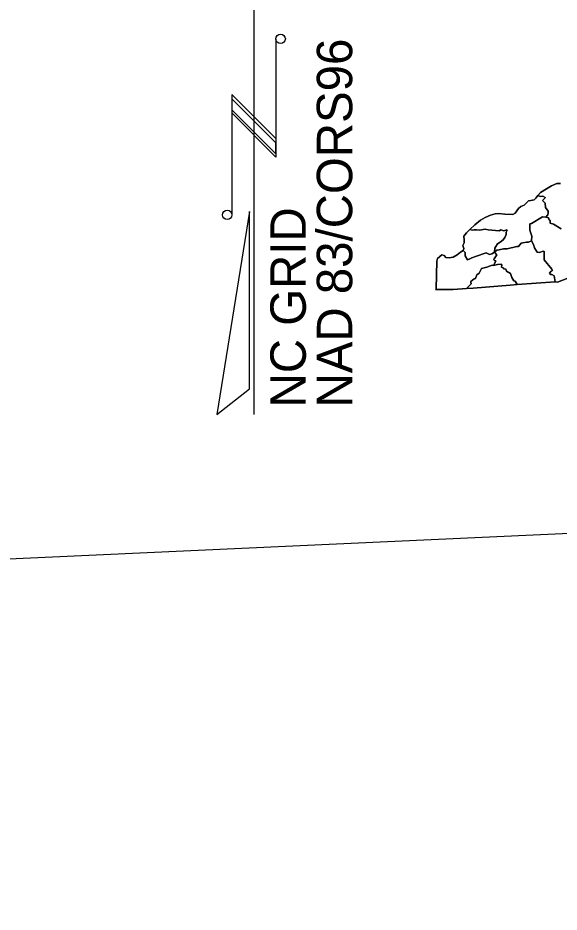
# Model space of a CAD drawing. Extents: x 1190067 to 1192950, y 891516 to 893460.
# Drawn here: x 1192773 to 1192834.1, y 893192.4 to 893293.3 of the extents above; entities that cross this region are included whole.
import ezdxf

# ---------------------------------------------------------------- set-up
doc = ezdxf.new("R2010")
doc.units = 0
for name, color, linetype in [('Old_Level_11', 7, 'Continuous'), ('Scratch_Level_3', 7, 'Continuous'), ('Sheet North Arrow CELL', 7, 'Continuous')]:
    doc.layers.add(name, color=color, linetype=linetype)

msp = doc.modelspace()

# ---------------------------------------------------------------- linework, layer by layer
at = {"layer": 'Old_Level_11'}
for points in [[(1192834.26, 893274.61), (1192833.86, 893274.64), (1192833.26, 893274.35), (1192832.66, 893274.02), (1192832.01, 893273.62), (1192831.68, 893273.25), (1192831.47, 893272.98), (1192831.27, 893272.77), (1192830.92, 893272.72), (1192830.63, 893272.68), (1192830.4, 893272.42), (1192830.16, 893272.16), (1192829.78, 893272.01), (1192829.51, 893271.79), (1192829.14, 893271.28), (1192828.86, 893271.14), (1192827.97, 893271.17), (1192827.27, 893271.22), (1192826.9, 893271.21), (1192826.36, 893271.05), (1192825.77, 893270.79), (1192825.22, 893270.5), (1192824.6, 893269.97), (1192824.04, 893269.44), (1192823.65, 893269.07), (1192823.36, 893268.67), (1192823.4, 893268.24), (1192823.38, 893267.91), (1192823.25, 893267.62), (1192823.36, 893267.3), (1192823.28, 893267.07), (1192822.98, 893266.89), (1192822.58, 893266.57), (1192822.16, 893266.32), (1192821.68, 893266.23), (1192821.32, 893266.28), (1192821.14, 893266.5), (1192820.86, 893266.57), (1192820.39, 893266.15), (1192820.31, 893265.87), (1192820.23, 893262.75), (1192820.16, 893262.66), (1192822.14, 893262.67), (1192823.64, 893262.76), (1192824.41, 893262.81), (1192828.59, 893263.15), (1192829.35, 893263.22), (1192833.64, 893263.54), (1192833.91, 893263.49), (1192835.08, 893263.95)], [(1192834.32, 893269.49), (1192833.47, 893270.04), (1192833.08, 893270.13), (1192833.1, 893270.44), (1192832.99, 893270.53), (1192832.9, 893270.74), (1192832.62, 893270.81), (1192832.81, 893271.09), (1192832.86, 893271.32), (1192832.86, 893271.51), (1192832.57, 893271.91), (1192832.54, 893272.39), (1192832.23, 893272.72), (1192832.32, 893272.83), (1192832.52, 893272.99), (1192832.54, 893273.06), (1192832.28, 893273.19), (1192831.97, 893273.15), (1192831.68, 893273.25), (1192832.01, 893273.62), (1192832.66, 893274.02), (1192833.26, 893274.35), (1192833.86, 893274.64), (1192834.26, 893274.61)], [(1192828.21, 893269.38), (1192827.87, 893269.27), (1192827.51, 893269.38), (1192827.34, 893269.28), (1192826.91, 893269.32), (1192826.11, 893269.39), (1192825.76, 893269.47), (1192825.1, 893269.34), (1192824.78, 893269.41), (1192824.5, 893269.4), (1192824.3, 893269.36), (1192824.04, 893269.44), (1192824.6, 893269.97), (1192825.22, 893270.5), (1192825.77, 893270.79), (1192826.36, 893271.05), (1192826.9, 893271.21), (1192827.27, 893271.22), (1192827.97, 893271.17), (1192828.86, 893271.14), (1192829.14, 893271.28), (1192829.51, 893271.79), (1192829.78, 893272.01), (1192830.16, 893272.16), (1192830.4, 893272.42), (1192830.63, 893272.68), (1192830.92, 893272.72), (1192831.27, 893272.77), (1192831.47, 893272.98), (1192831.68, 893273.25), (1192831.97, 893273.15), (1192832.28, 893273.19), (1192832.54, 893273.06), (1192832.52, 893272.99), (1192832.32, 893272.83), (1192832.23, 893272.72), (1192832.54, 893272.39), (1192832.57, 893271.91), (1192832.86, 893271.51), (1192832.86, 893271.32), (1192832.81, 893271.09), (1192832.62, 893270.81), (1192832.22, 893270.87), (1192831, 893270.1), (1192830.78, 893270.07), (1192830.8, 893269.36), (1192830.96, 893268.92), (1192831.03, 893268.67), (1192831, 893268.14), (1192830.63, 893268.01), (1192830.42, 893268.02), (1192830.02, 893267.91), (1192829.81, 893267.89), (1192829.53, 893267.53), (1192829.32, 893267.5), (1192828.25, 893267.26), (1192827.82, 893267.25), (1192827.35, 893267.14), (1192827.08, 893267.1), (1192826.81, 893266.88), (1192826.86, 893267.32), (1192826.97, 893267.51), (1192827.16, 893267.8), (1192827.46, 893268.01), (1192827.8, 893268.26), (1192827.96, 893268.51), (1192828.11, 893268.88), (1192828.13, 893269.13), (1192828.24, 893269.34), (1192828.21, 893269.38)], [(1192835.08, 893263.95), (1192833.91, 893263.49), (1192833.64, 893263.54), (1192833.55, 893264.22), (1192833.29, 893264.36), (1192833.11, 893264.37), (1192833.03, 893264.5), (1192833.2, 893264.72), (1192833.37, 893264.82), (1192833.27, 893264.95), (1192832.42, 893265.99), (1192832.41, 893266.96), (1192832.29, 893266.98), (1192831.87, 893266.85), (1192831.63, 893266.86), (1192831.32, 893267.38), (1192831.21, 893267.75), (1192831, 893268.14), (1192831.03, 893268.67), (1192830.96, 893268.92), (1192830.8, 893269.36), (1192830.78, 893270.07), (1192831, 893270.1), (1192832.22, 893270.87)], [(1192832.22, 893270.87), (1192832.62, 893270.81), (1192832.9, 893270.74), (1192832.99, 893270.53), (1192833.1, 893270.44), (1192833.08, 893270.13), (1192833.47, 893270.04), (1192834.32, 893269.49)], [(1192826.81, 893266.88), (1192826.51, 893266.68), (1192826.24, 893266.6), (1192825.85, 893266.78), (1192824.65, 893266.39), (1192824.26, 893266.24), (1192824.04, 893266.13), (1192823.77, 893266.01), (1192823.48, 893266.46), (1192823.48, 893266.82), (1192823.28, 893267.07), (1192823.36, 893267.3), (1192823.25, 893267.62), (1192823.38, 893267.91), (1192823.4, 893268.24), (1192823.36, 893268.67), (1192823.65, 893269.07), (1192824.04, 893269.44), (1192824.3, 893269.36), (1192824.5, 893269.4), (1192824.78, 893269.41), (1192825.1, 893269.34), (1192825.76, 893269.47), (1192826.11, 893269.39), (1192826.91, 893269.32), (1192827.34, 893269.28), (1192827.51, 893269.38), (1192827.87, 893269.27), (1192828.21, 893269.38), (1192828.24, 893269.34), (1192828.13, 893269.13), (1192828.11, 893268.88), (1192827.96, 893268.51), (1192827.8, 893268.26), (1192827.46, 893268.01), (1192827.16, 893267.8), (1192826.97, 893267.51), (1192826.86, 893267.32), (1192826.81, 893266.88)], [(1192830.63, 893268.01), (1192831, 893268.14), (1192831.21, 893267.75), (1192831.32, 893267.38), (1192831.63, 893266.86), (1192831.87, 893266.85), (1192832.29, 893266.98), (1192832.41, 893266.96), (1192832.42, 893265.99), (1192833.27, 893264.95), (1192833.37, 893264.82), (1192833.2, 893264.72), (1192833.03, 893264.5), (1192833.11, 893264.37), (1192833.29, 893264.36), (1192833.55, 893264.22), (1192833.64, 893263.54), (1192829.35, 893263.22), (1192829.13, 893263.6), (1192829, 893263.65), (1192828.76, 893264.03), (1192828.62, 893264.48), (1192828.16, 893264.72), (1192828.09, 893264.96), (1192827.86, 893264.99), (1192827.79, 893265.11), (1192827.6, 893265.17), (1192827.63, 893265.4), (1192827.56, 893265.52), (1192827.15, 893265.48), (1192826.71, 893265.37), (1192826.85, 893265.64), (1192826.97, 893265.9), (1192826.8, 893265.94), (1192826.72, 893265.99), (1192826.78, 893266.11), (1192827.08, 893266.58), (1192826.81, 893266.88), (1192827.08, 893267.1), (1192827.35, 893267.14), (1192827.82, 893267.25), (1192828.25, 893267.26), (1192829.32, 893267.5), (1192829.53, 893267.53), (1192829.81, 893267.89), (1192830.02, 893267.91), (1192830.42, 893268.02), (1192830.63, 893268.01)], [(1192826.81, 893266.88), (1192827.08, 893266.58), (1192826.78, 893266.11), (1192826.72, 893265.99), (1192826.8, 893265.94), (1192826.97, 893265.9), (1192826.85, 893265.64), (1192826.71, 893265.37), (1192826.54, 893265.42), (1192825.93, 893265.18), (1192825.34, 893265.03), (1192825.07, 893264.52), (1192824.83, 893264.3), (1192824.65, 893263.92), (1192824.51, 893263.86), (1192824.13, 893263.57), (1192824.14, 893263.5), (1192824.16, 893263.31), (1192823.64, 893262.76), (1192822.14, 893262.67), (1192820.16, 893262.66), (1192820.23, 893262.75), (1192820.31, 893265.87), (1192820.39, 893266.15), (1192820.86, 893266.57), (1192821.14, 893266.5), (1192821.32, 893266.28), (1192821.68, 893266.23), (1192822.16, 893266.32), (1192822.58, 893266.57), (1192822.98, 893266.89), (1192823.28, 893267.07), (1192823.48, 893266.82), (1192823.48, 893266.46), (1192823.77, 893266.01), (1192824.04, 893266.13), (1192824.26, 893266.24), (1192824.65, 893266.39), (1192825.85, 893266.78), (1192826.24, 893266.6), (1192826.51, 893266.68), (1192826.81, 893266.88)], [(1192827.56, 893265.52), (1192827.63, 893265.4), (1192827.6, 893265.17), (1192827.79, 893265.11), (1192827.86, 893264.99), (1192828.09, 893264.96), (1192828.16, 893264.72), (1192828.62, 893264.48), (1192828.76, 893264.03), (1192829, 893263.65), (1192829.13, 893263.6), (1192829.35, 893263.22), (1192828.59, 893263.15), (1192824.41, 893262.81), (1192823.64, 893262.76), (1192824.16, 893263.31), (1192824.14, 893263.5), (1192824.13, 893263.57), (1192824.51, 893263.86), (1192824.65, 893263.92), (1192824.83, 893264.3), (1192825.07, 893264.52), (1192825.34, 893265.03), (1192825.93, 893265.18), (1192826.54, 893265.42), (1192826.71, 893265.37), (1192827.15, 893265.48), (1192827.56, 893265.52)]]:
    msp.add_lwpolyline(points, dxfattribs=at)
at = {"layer": 'Scratch_Level_3'}
msp.add_lwpolyline([(1192415.45, 893028.46), (1192896.45, 893050.47), (1192887.89, 893237.54), (1192406.89, 893215.53)], close=True, dxfattribs=at)
at = {"layer": 'Sheet North Arrow CELL'}
for p, q in [((1192799.69, 893248.57), (1192799.69, 893313.57)), ((1192802.14, 893290.95), (1192802.14, 893277.61)), ((1192802.14, 893279.69), (1192797.17, 893284.66)), ((1192797.17, 893284.66), (1192797.17, 893271.1)), ((1192802.14, 893279.2), (1192797.17, 893284.17)), ((1192797.17, 893284.17), (1192797.17, 893282.95)), ((1192802.14, 893277.98), (1192797.17, 893282.95)), ((1192797.17, 893282.95), (1192802.14, 893277.98)), ((1192802.14, 893277.61), (1192797.17, 893282.58)), ((1192802.14, 893277.98), (1192802.14, 893279.2))]:
    msp.add_line(p, q, dxfattribs=at)
msp.add_lwpolyline([(1192799.16, 893271.47), (1192795.48, 893248.57), (1192799.16, 893251.47)], close=True, dxfattribs=at)
for centre in [(1192802.67, 893290.94), (1192796.64, 893271.08)]:
    msp.add_circle(centre, 0.53, dxfattribs=at)

# ---------------------------------------------------------------- texts
for s, p in [('NAD 83/CORS96', (1192810.75, 893249.35)), ('NC GRID', (1192805.51, 893249.35))]:
    msp.add_text(s, height=4, rotation=90, dxfattribs=at).set_placement(p)

doc.saveas('drawing.dxf')
